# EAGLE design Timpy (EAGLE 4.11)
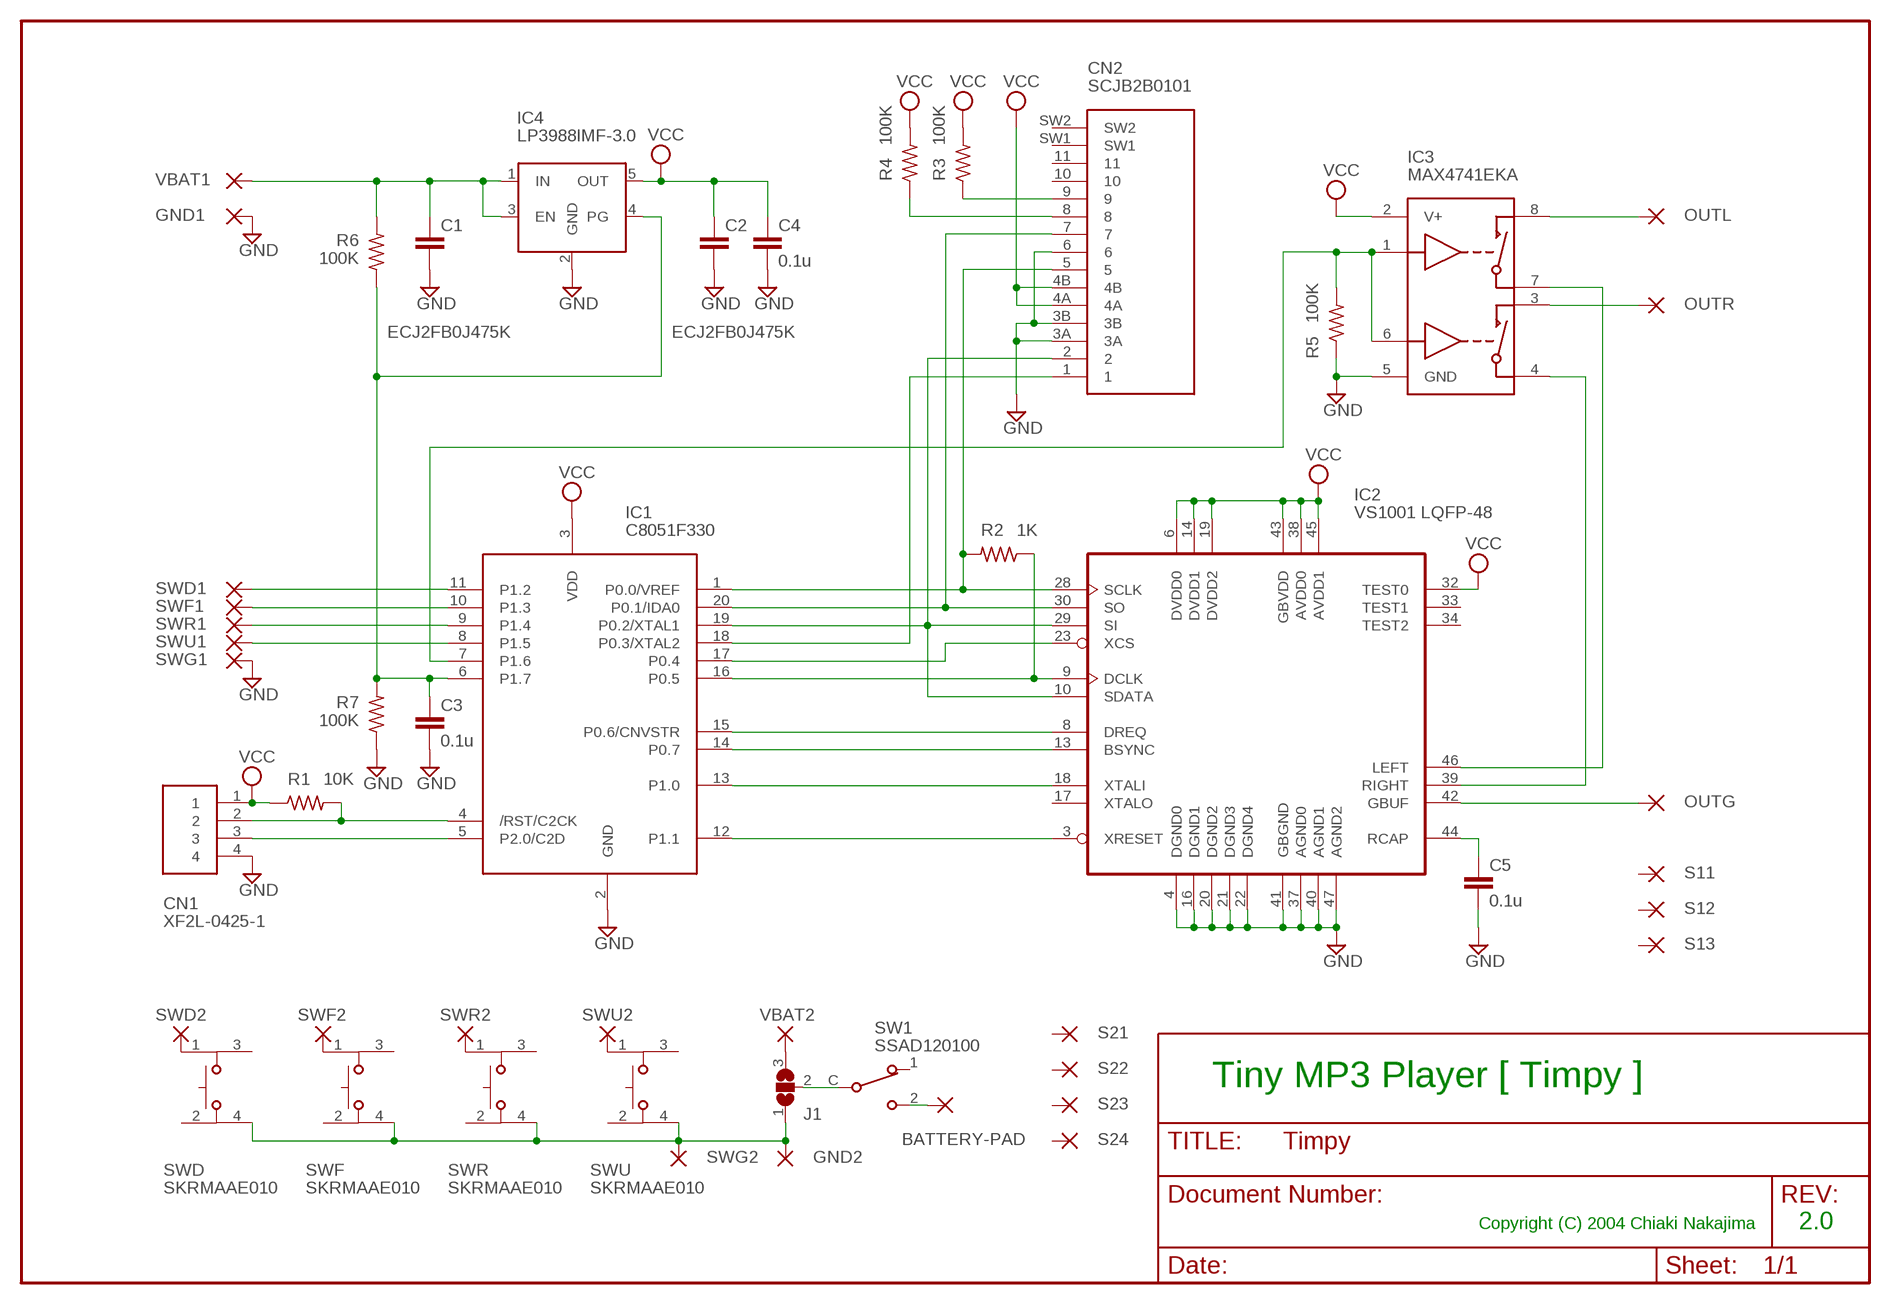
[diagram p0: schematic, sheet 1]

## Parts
BATTERY-PAD  SMD2  [SMD2]
C1  ECJ2FB0J475K  C-EUC2012  [C2012]
C2  ECJ2FB0J475K  C-EUC2012  [C2012]
C3  0.1u  C-EUC1005  [C1005]
C4  0.1u  C-EUC1005  [C1005]
C5  0.1u  C-EUC1005  [C1005]
CN1  XF2L-0425-1  [XF2L-0425-1]
CN2  SCJB2B0101  SCJB2B010X  [SCJB2B010X]
GND1  0.6/0.45  [0.6/0.45]
GND2  0.6/0.45  [0.6/0.45]
IC1  C8051F330  C8051F33X  [MLP20]
IC2  VS1001 LQFP-48  VS1001-LQFP48  [LQFP-48]
IC3  MAX4741EKA  [SOT23-8L]
IC4  LP3988IMF-3.0  LP3988  [SOT23-5]
J1  SMD-J3  [SMD-J3-1005X2]
OUTG  0.6/0.45  [0.6/0.45]
OUTL  0.6/0.45  [0.6/0.45]
OUTR  0.6/0.45  [0.6/0.45]
R1  10K  R-US_R1005  [R1005]
R2  1K  R-US_R1005  [R1005]
R3  100K  R-US_R1005  [R1005]
R4  100K  R-US_R1005  [R1005]
R5  100K  R-US_R1005  [R1005]
R6  100K  R-US_R1005  [R1005]
R7  100K  R-US_R1005  [R1005]
S11  0.6/0.45  [0.6/0.45]
S12  0.6/0.45  [0.6/0.45]
S13  0.6/0.45  [0.6/0.45]
S21  0.6/0.45  [0.6/0.45]
S22  0.6/0.45  [0.6/0.45]
S23  0.6/0.45  [0.6/0.45]
S24  0.6/0.45  [0.6/0.45]
SW1  SSAD120100  [SSAD120100]
SWD  SKRMAAE010  [SKRMAAE010]
SWD1  0.6/0.45  [0.6/0.45]
SWD2  0.6/0.45  [0.6/0.45]
SWF  SKRMAAE010  [SKRMAAE010]
SWF1  0.6/0.45  [0.6/0.45]
SWF2  0.6/0.45  [0.6/0.45]
SWG1  0.6/0.45  [0.6/0.45]
SWG2  0.6/0.45  [0.6/0.45]
SWR  SKRMAAE010  [SKRMAAE010]
SWR1  0.6/0.45  [0.6/0.45]
SWR2  0.6/0.45  [0.6/0.45]
SWU  SKRMAAE010  [SKRMAAE010]
SWU1  0.6/0.45  [0.6/0.45]
SWU2  0.6/0.45  [0.6/0.45]
VBAT1  0.6/0.45  [0.6/0.45]
VBAT2  0.6/0.45  [0.6/0.45]

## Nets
BATTERY-PAD: BATTERY-PAD.1(P) SW1.2
GND: C1.2 C2.2 C3.2 C4.2 C5.2 CN1.4 CN2.3A CN2.3B CN2.6 GND1.P$1(P) IC1.2(GND) IC2.4(DGND0) IC2.16(DGND1) IC2.20(DGND2) IC2.21(DGND3) IC2.22(DGND4) IC2.37(AGND0) IC2.40(AGND1) IC2.41(GBGND) IC2.47(AGND2) IC3.5(GND) IC4.2(GND) R5.1 R7.1 SWG1.P$1(P)
GND2 [Power]: GND2.P$1(P) J1.1 SWD.4 SWF.4 SWG2.P$1(P) SWR.4 SWU.4
N$1: CN1.3 IC1.5(P2.0/C2D)
N$2: SWD2.P$1(P) SWD.1
N$3: CN1.2 IC1.4(/RST/C2CK) R1.2
N$4: CN2.9 R3.1
N$5: CN2.8 R4.1
N$6: CN2.5 IC1.1(P0.0/VREF) IC2.28(SCLK) R2.2
N$7: IC1.16(P0.5) IC2.9(DCLK) R2.1
N$8: CN2.7 IC1.20(P0.1/IDA0) IC2.30(SO)
N$9: CN2.2 IC1.19(P0.2/XTAL1) IC2.10(SDATA) IC2.29(SI)
N$10: CN2.1 IC1.18(P0.3/XTAL2)
N$11: IC1.17(P0.4) IC2.23(XCS)
N$12: IC1.15(P0.6/CNVSTR) IC2.8(DREQ)
N$13: IC1.14(P0.7) IC2.13(BSYNC)
N$14: IC1.13(P1.0) IC2.18(XTALI)
N$15: IC1.12(P1.1) IC2.3(XRESET)
N$16: IC1.7(P1.6) IC3.1(IN1) IC3.6(IN2) R5.2
N$17 [Analog Out]: IC2.46(LEFT) IC3.7(COM1)
N$18 [Analog Out]: IC2.39(RIGHT) IC3.4(COM2)
N$19: C3.1 IC1.6(P1.7) IC4.4(PG) R6.1 R7.2
N$20: C5.1 IC2.44(RCAP)
N$22: C1.1 IC4.1(IN) IC4.3(EN) R6.2 VBAT1.P$1(P)
N$23 [Analog Out]: IC2.42(GBUF) OUTG.P$1(P)
N$24 [Analog Out]: IC3.8(NO1) OUTL.P$1(P)
N$25 [Analog Out]: IC3.3(NO2) OUTR.P$1(P)
N$26: IC1.11(P1.2) SWD1.P$1(P)
N$27: IC1.10(P1.3) SWF1.P$1(P)
N$28: IC1.9(P1.4) SWR1.P$1(P)
N$29: IC1.8(P1.5) SWU1.P$1(P)
N$30: SWF2.P$1(P) SWF.1
N$31: SWR2.P$1(P) SWR.1
N$32: SWU2.P$1(P) SWU.1
N$34 [Power]: J1.2 SW1.C
N$35 [Power]: J1.3 VBAT2.P$1(P)
VCC [Power]: C2.1 C4.1 CN1.1 CN2.4A CN2.4B IC1.3(VDD) IC2.6(DVDD0) IC2.14(DVDD1) IC2.19(DVDD2) IC2.32(TEST0) IC2.38(AVDD0) IC2.43(GBVDD) IC2.45(AVDD1) IC3.2(V+) IC4.5(OUT) R1.1 R3.2 R4.2
Unconnected: CN2.10 CN2.11 CN2.SW1 CN2.SW2 IC2.17(XTALO) IC2.33(TEST1) IC2.34(TEST2) S11.P$1(P) S12.P$1(P) S13.P$1(P) S21.P$1(P) S22.P$1(P) S23.P$1(P) S24.P$1(P) SW1.1 SWD.2 SWD.3 SWF.2 SWF.3 SWR.2 SWR.3 SWU.2 SWU.3

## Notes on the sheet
- Tiny MP3 Player [ Timpy ]
- Copyright (C) 2004 Chiaki Nakajima | 2.0

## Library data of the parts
BATTERY-PAD = wirepad:SMD2: SMD PAD
C1-C5 = rcl:C-EU: CAPACITOR, European symbol
CN1 = conn-omron-xf2l:XF2L-0425-1: 4P
CN2 = conn-alps-miniSD:SCJB2B010X: SCJB2B0101/2 miniSD connector
GND1 GND2 OUTG OUTL OUTR S11-S13 S21-S24 SWD1 SWD2 SWF1 SWF2 SWG1 SWG2 SWR1 SWR2 SWU1 SWU2 VBAT1 VBAT2 = pads:0.6/0.45: 0.6mm/0.45mm Through-Hole Pad
IC1 = cygnal_33x:C8051F33X: Cygnal C8051F330/1 microcontroller
IC2 = vs1001-lqfp:VS1001-LQFP48: VS1001 MP3 Decoder (LQFP-48)
IC3 = max4741:MAX4741E: Dual SPST Analog Switches on SOT23-8 Package
IC4 = lp3988:LP3988: National Semiconductor LP3988 Jul 07, 2004 Chiaki Nakajima http://www.chiaki.cc chi@chiaki.cc
J1 = pads:SMD-J3: SMD Jumper 3P
R1-R7 = rcl:R-US_: RESISTOR, American symbol
SW1 = switch-alps-tact:SSAD120100: Slide Switch SPDT SSAD120100
SWD SWF SWR SWU = switch-alps-tact:SKRMAAE010: Tact Switch SKRMAAE010

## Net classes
1 Analog Out: width 0.2 mm
2 Power: width 0.3 mm

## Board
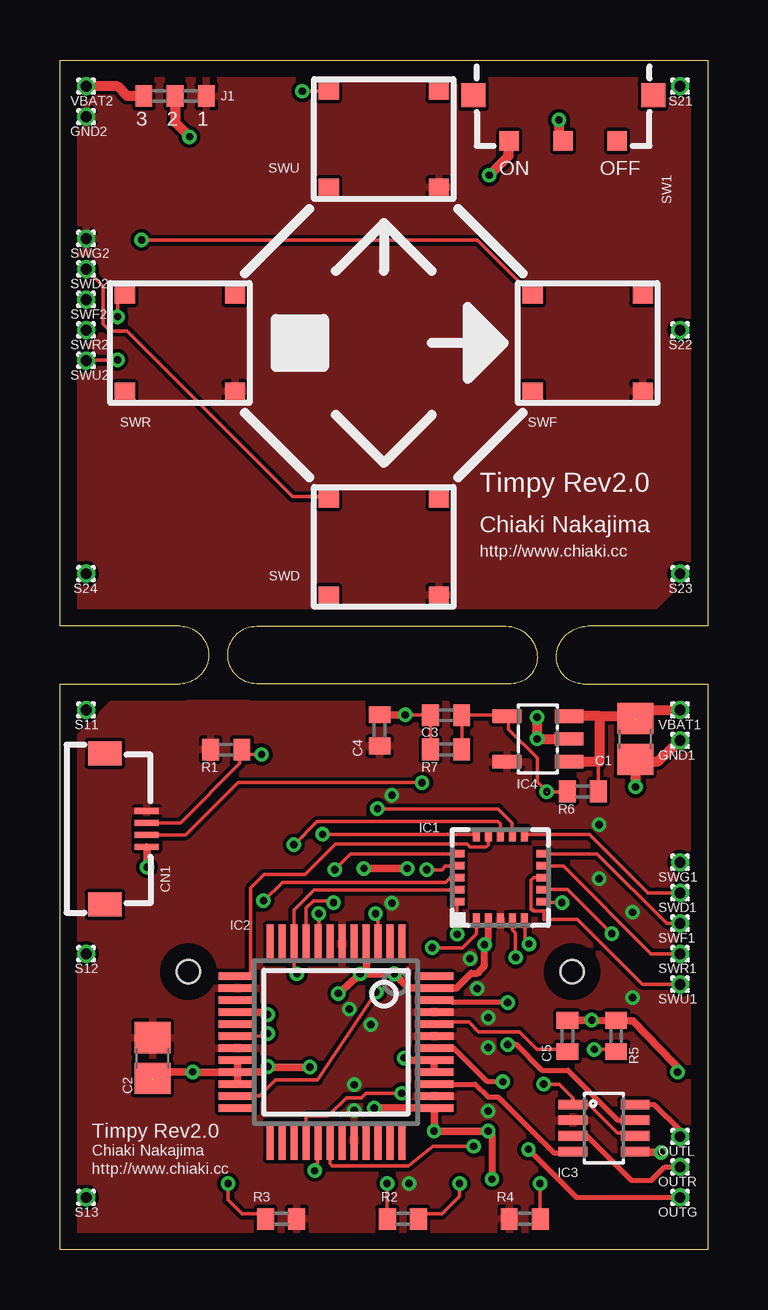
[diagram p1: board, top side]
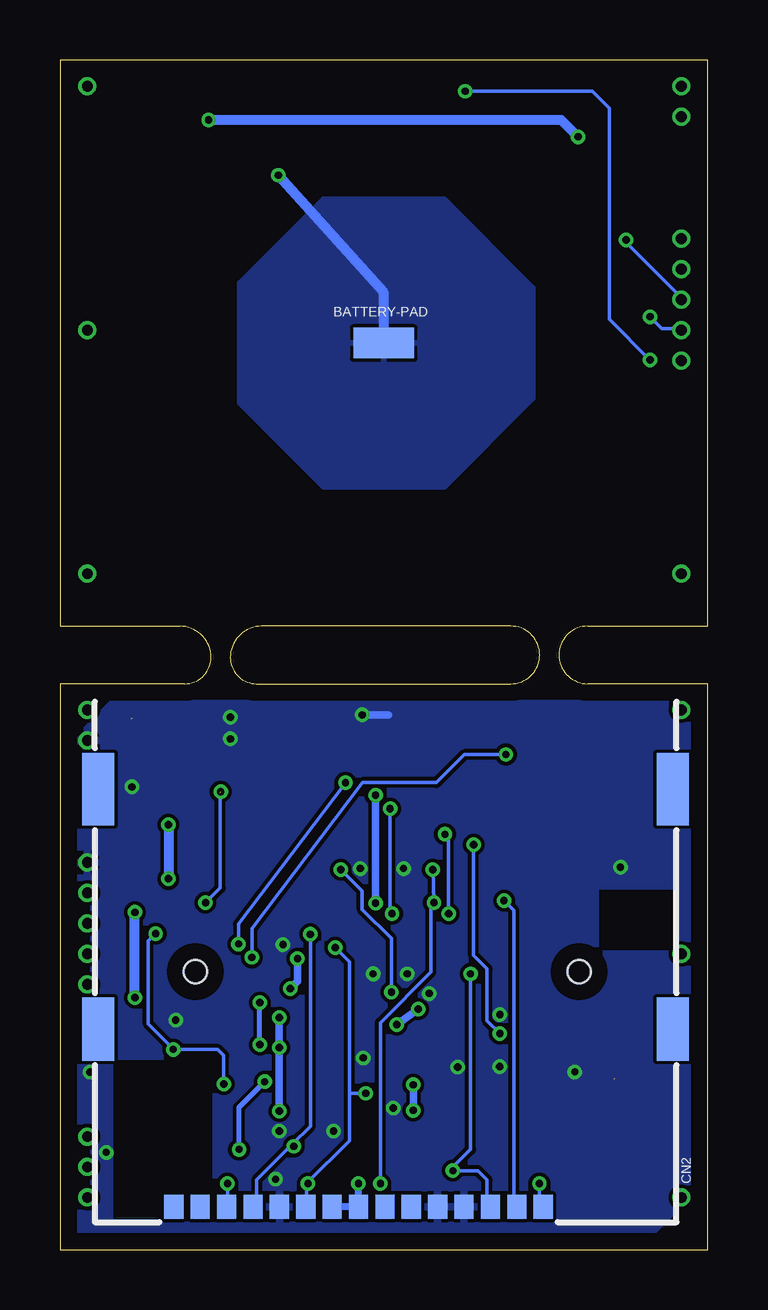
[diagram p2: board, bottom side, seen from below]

Size 27 x 49.6 mm. Coordinates in mm from the lower left corner, seen from the top.
Outline: 0,0 0,23.6 5,23.6 arc90 6.2,24.8 arc90 5,26 0,26 0,49.6 27,49.6 27,26 22,26 arc90 20.7,24.7 arc90 21.8,23.6 27,23.6 27,0 0,0
Outline: 7,24.8 arc-90 8.2,26 18.6,26 arc-90 19.9,24.7 arc-90 18.8,23.6 8.2,23.6 arc-90 7,24.8
Copper layers (1*16): Top 0.035mm / dielectric 1.5mm / Bottom 0.035mm
Design rules "p-ban": minimum track width 0.15mm, minimum drill 0.3mm, track to track 0.15mm, track to pad 0.15mm, pad to pad 0.15mm, via to via 0.15mm, smd to smd 0.15mm, copper to edge 0.7mm, drill to drill 0.45mm, minimum pad ring 0.15mm, minimum via ring 0.15mm, stop-mask expansion 4mil, vias tented up to drill 0mil, thermal gap 0.15mm

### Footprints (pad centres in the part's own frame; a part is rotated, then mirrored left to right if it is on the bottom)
SMD2 = smd 1.27 x 2.54: 1 0,0
C2012 = smd 1.3 x 1.5: 1 -0.85,0; 2 0.85,0
C1005 = smd 0.7 x 0.9: 1 -0.65,0; 2 0.65,0
XF2L-0425-1 = smd 0.25 x 1: 1 -0.75,0.5; 2 -0.25,0.5; 3 0.25,0.5; 4 0.75,0.5 | smd 1 x 1.4: F1 -3.15,-1.25; F2 3.15,-1.25
SCJB2B010X = smd 0.8 x 1: 1 -6.35,0; 2 -5.25,0; 3A -4.15,0; 3B -3.05,0; 4A 0.25,0; 4B 1.35,0; 5 2.45,0; 6 3.55,0; 7 4.65,0; 8 5.75,0; 9 -7.45,0; 10 -1.95,0; 11 -0.85,0; SW1 6.85,0; SW2 7.95,0 | smd 1.35 x 2.6: F1 -12.85,-7.4; F2 11.1,-7.4 | smd 1.35 x 3: F3 -12.85,-17.4; F4 11.1,-17.4 | hole 0.95: 7.05,-9.8; -8.95,-9.8
0.6/0.45 = drill 0.45 pad 0.6 round: P$1 0,0
MLP20 = smd 0.6 x 0.3: 1 -1.8,1; 2 -1.8,0.5; 3 -1.8,0; 4 -1.8,-0.5; 5 -1.8,-1; 11 1.8,-1; 12 1.8,-0.5; 13 1.8,0; 14 1.8,0.5; 15 1.8,1 | smd 0.3 x 0.6: 6 -1,-1.8; 7 -0.5,-1.8; 8 0,-1.8; 9 0.5,-1.8; 10 1,-1.8; 16 1,1.8; 17 0.5,1.8; 18 0,1.8; 19 -0.5,1.8; 20 -1,1.8
LQFP-48 = smd 0.3 x 1.6: 1 -2.75,-4.1; 2 -2.25,-4.1; 3 -1.75,-4.1; 4 -1.25,-4.1; 5 -0.75,-4.1; 6 -0.25,-4.1; 7 0.25,-4.1; 8 0.75,-4.1; 9 1.25,-4.1; 10 1.75,-4.1; 11 2.25,-4.1; 12 2.75,-4.1; 25 2.75,4.1; 26 2.25,4.1; 27 1.75,4.1; 28 1.25,4.1; 29 0.75,4.1; 30 0.25,4.1; 31 -0.25,4.1; 32 -0.75,4.1; 33 -1.25,4.1; 34 -1.75,4.1; 35 -2.25,4.1; 36 -2.75,4.1 | smd 1.6 x 0.3: 13 4.1,-2.75; 14 4.1,-2.25; 15 4.1,-1.75; 16 4.1,-1.25; 17 4.1,-0.75; 18 4.1,-0.25; 19 4.1,0.25; 20 4.1,0.75; 21 4.1,1.25; 22 4.1,1.75; 23 4.1,2.25; 24 4.1,2.75; 37 -4.1,2.75; 38 -4.1,2.25; 39 -4.1,1.75; 40 -4.1,1.25; 41 -4.1,0.75; 42 -4.1,0.25; 43 -4.1,-0.25; 44 -4.1,-0.75; 45 -4.1,-1.25; 46 -4.1,-1.75; 47 -4.1,-2.25; 48 -4.1,-2.75
SOT23-8L = smd 0.4 x 1.2: 1 -0.95,-1.3; 2 -0.3,-1.3; 3 0.35,-1.3; 4 1,-1.3; 5 1,1.3; 6 0.35,1.3; 7 -0.3,1.3; 8 -0.95,1.3
SOT23-5 = smd 0.55 x 1.2: 1 -0.95,-1.3; 2 0,-1.3; 3 0.95,-1.3; 4 0.95,1.3; 5 -0.95,1.3
SMD-J3-1005X2 = smd 0.7 x 0.9: 1 -1.3,0; 2 0,0; 3 1.3,0
R1005 = smd 0.7 x 0.9: 1 -0.65,0; 2 0.65,0
SSAD120100 = smd 0.8 x 0.8: 1 -2.25,1.9; 2 2.25,1.9; C 0,1.9 | smd 1 x 1: F1 -3.75,0; F2 3.75,0
SKRMAAE010 = smd 0.85 x 0.7: 1 -2.3,2; 2 -2.3,-2; 3 2.3,2; 4 2.3,-2

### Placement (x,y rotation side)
BATTERY-PAD  13.5,37.8 270 bottom
C1  23.98,21.3 270 top
C2  3.86,8 270 top
C3  16.1,22.29 180 top
C4  13.33,21.66 90 top
C5  21.16,8.92 90 top
CN1  3.12,17.55 270 top
CN2  14.3,1.8 180 bottom
GND1  25.86,21.23 180 top
GND2  1.09,47.23 180 top
IC1  18.36,15.52 90 top
IC2  11.51,8.66 180 top
IC3  22.68,5.11 270 top
IC4  19.93,21.3 90 top
J1  4.8,48.1 180 top
OUTG  25.86,2.18 180 top
OUTL  25.86,4.72 180 top
OUTR  25.86,3.45 180 top
R1  6.93,20.85 0 top
R2  14.3,1.3 0 top
R3  9.22,1.3 0 top
R4  19.38,1.3 180 top
R5  23.19,8.92 270 top
R6  21.8,19.11 0 top
R7  16.1,20.86 0 top
S11  1.09,22.5 180 top
S12  1.09,12.34 180 top
S13  1.09,2.18 180 top
S21  25.86,48.5 180 top
S22  25.86,38.34 180 top
S23  25.86,28.18 180 top
S24  1.09,28.18 180 top
SW1  20.98,48.12 180 top
SWD  13.5,29.3 0 top
SWD1  25.86,14.88 180 top
SWD2  1.09,40.88 180 top
SWF  22,37.8 0 top
SWF1  25.86,13.61 180 top
SWF2  1.09,39.61 180 top
SWG1  25.86,16.15 180 top
SWG2  1.09,42.15 180 top
SWR  5,37.8 0 top
SWR1  25.86,12.34 180 top
SWR2  1.09,38.34 180 top
SWU  13.5,46.3 0 top
SWU1  25.86,11.07 180 top
SWU2  1.09,37.07 180 top
VBAT1  25.86,22.5 180 top
VBAT2  1.09,48.5 180 top

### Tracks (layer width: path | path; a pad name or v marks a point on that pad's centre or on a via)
BATTERY-PAD  (via drill 0.3)
  Top 0.406: SW1.2 18.7,45.6 v17.9,44.8
  Bottom 0.406: v17.9,44.8 13.5,39.9 BATTERY-PAD.1
  pour Bottom: 11,43.8 7.3,40.1 7.3,35.5 11,31.8 16,31.8 19.5,35.3 19.5,40.3 16,43.8
GND  (via drill 0.3)  (1 unrouted)
  Top 0.15: v14.4,22.3 15.4,22.3 | 15.4,22.3 15.5,22.3 15.49,22.29 C3.2 15.41,22.29 15.4,22.3 | R7.1 15.45,22.25 15.4,22.3
  Top 0.3: IC1.2 17.86,12.98 v17.7,12.72 17.7,11.86 17.4,11.53 17.14,11.53 16.54,10.92 16.38,10.92 | v18.01,2.95 18.01,4.8 v17.86,4.95
  Top 0.305: IC2.40 15.6,7.54 15.6,7.77 IC2.41 14.45,7.9 v14.35,8 | 23.88,9.55 23.77,9.55 23.15,9.56 R5.1 | 23.88,9.55 25.6,7.77 25.76,7.62 v25.76,7.42 | 23.88,9.55 v22.17,9.58 21.59,9.58 C5.2 | v3.63,15.95 3.63,16.51 CN1.4 | v25.07,4.06 24.31,4.06 IC3.5 | 12.78,11.51 IC2.4 | v8.66,9.8 8.56,9.91 IC2.16 | 12.78,11.51 v13.95,11.51 14.53,10.92 16.08,10.92 | IC2.37 15.61,4.96 v15.6,4.95 v17.86,4.95 | 12.78,11.51 v12.52,11.51 v11.61,10.69 | IC2.21 8.46,7.42 8.66,7.62 | 8.66,7.62 v8.66,7.64 | 3.89,7.11 4.19,7.42 v5.54,7.42 v5.54,7.41 IC2.21 | IC2.20 7.39,7.9 7.41,7.88 | IC2.21 7.41,7.88 | IC2.21 IC2.22 | IC2.21 7.41,7.43 7.39,7.44 7.41,7.46 7.41,7.88 | 8.66,7.62 v10.41,7.62 | v13.11,5.92 15.62,5.92 | 16.08,10.92 16.38,10.92 | IC2.47 16.07,10.91 16.08,10.92 | v12.68,15.9 v14.48,15.9 | C4.2 v14.4,22.3
  Top 0.406: 23.93,20.26 24.03,20.26 24.4,20.28 24.4,20.36 24.96,20.36 GND1.P$1 | C1.2 24,19.95 v24,19.3 | v19.9,22.2 v19.9,21.3 IC4.2
  Bottom 0.305: 14.21,22.3 14.42,22.32 | 14.21,22.3 13.3,22.3 | v14.4,22.3 14.21,22.3
  pour Bottom: 26.77,20.83 26.77,0.25 2.79,0.25 0.25,2.79 0.25,22.77 24.83,22.77
GND2
  pour Top: 0.25,26.85 0.25,46.83 2.79,49.37 26.77,49.37 26.77,28.79 24.83,26.85
N$1  (via drill 0.3)
  Top 0.15: v15.1,19.47 15.09,19.48 7.42,19.48 5.23,17.3 CN1.3 | v19.56,12.75 19.38,12.93 19.38,13.72 IC1.5
  Bottom 0.15: v19.56,12.75 19.56,13.59 v15.1,19.47
N$2
  Top 0.15: SWD2.P$1 1.8,40.18 1.8,38.6 2.1,38.3 2.8,38.3 9.7,31.4 11.1,31.4 SWD.1
N$3  (via drill 0.3)  (1 unrouted)
  Top 0.15: v8.41,20.65 7.92,20.65 R1.2 7.49,20.42 7.49,20.27 5.03,17.8 CN1.2 | v19,12.19 19,13.18
  Top 0.152: IC1.4 18.86,13.34 19,13.21 19,13.18
  Bottom 0.15: v8.41,20.65 10.13,20.65 11.3,19.48 14.38,19.48 19,13.4 | v19,12.19 19,13.41
N$4  (via drill 0.3)
  Top 0.15: v7.01,2.77 7.01,2.08 7.59,1.5 8.23,1.5 R3.1
  Bottom 0.15: v7.01,2.77 7.01,2.29 CN2.9
N$5  (via drill 0.3)
  Top 0.15: v20.02,2.77 20.02,1.73 R4.1
  Bottom 0.15: v20.02,2.77 20.02,2.29 CN2.8
N$6  (via drill 0.3)
  Top 0.15: v15.52,12.6 16.79,12.6 17.36,13.17 IC1.1 | v16.66,2.77 16.66,2.23 15.93,1.5 15.29,1.5 R2.2 | v14.25,6.53 12.75,6.53 12.57,6.35 11.94,6.35 11.18,5.59 10.26,5.59 10.26,5.49 IC2.28
  Bottom 0.15: v15.52,12.6 14.94,12.01 14.94,6.53 | 16.71,2.77 16.71,2.29 CN2.5 | 14.94,6.53 14.94,4.55 16.71,2.77 | v16.66,2.77 16.71,2.77 | 14.94,6.53 v14.25,6.53
N$7  (via drill 0.3)
  Top 0.15: v11.46,15.85 12.12,16.51 16.38,16.51 IC1.16 | v11.4,14.48 11.33,14.55 10.57,14.55 10.26,14.25 10.26,13.54 IC2.9 | v13.64,2.77 13.64,1.73 R2.1
  Bottom 0.15: v11.46,15.85 11.4,14.53 v11.4,14.48 11.53,14.2 11.53,11.58 13.64,9.47 v13.64,2.77
N$8  (via drill 0.3)
  Top 0.15: v16.56,13.16 16.56,14.38 IC1.20 | v17.25,4.32 15.54,4.32 14.53,3.5 11.35,3.5 11.25,3.61 IC2.30
  Bottom 0.15: 16.56,13.08 v16.56,13.16 16.56,5.16 17.32,4.39 | 17.32,4.39 18.8,2.92 18.8,2.29 CN2.7 | v17.25,4.32 17.32,4.39
N$9  (via drill 0.3)
  Top 0.15: v10.62,3.3 10.62,3.5 10.74,3.63 10.74,3.79 IC2.29 | IC1.19 16.28,15.01 10.59,15.01 9.75,14.17 IC2.10 9.75,11.79 v9.88,11.51
  Bottom 0.15: CN2.2 9.2,2.29 9.2,2.92 9.58,3.3 v10.62,3.3 10.49,3.58 9.88,4.19 v9.88,11.51
N$10  (via drill 0.3)
  Top 0.15: IC1.18 16.28,15.52 16.08,15.32 9.27,15.32 v8.48,14.55
  Bottom 0.15: v8.48,14.55 8.08,14.15 8.08,2.29 CN2.1
N$11  (via drill 0.3)
  Top 0.15: v15.29,15.85 15.93,15.85 16.08,16 16.54,16 IC1.17 | v13.18,10.74 10.74,7.09 8.99,7.09 8.33,6.43 8.05,6.43 IC2.23
  Bottom 0.15: v15.29,15.85 14.4,14.96 14.4,14.2 13.18,12.98 v13.18,10.74
N$12  (via drill 0.3)
  Top 0.15: v10.95,17.32 17.22,17.32 IC1.15 | v10.79,14.02 10.79,13.54 IC2.8
  Bottom 0.15: v10.95,17.32 10.79,17.17 v10.79,14.02
N$13
  Top 0.15: IC1.14 17.86,16.89 17.75,16.79 17.09,16.79 16.97,16.92 11.48,16.92 10.21,15.65 8.51,15.65 7.95,15.09 7.95,11.4 IC2.13
N$14  (via drill 0.3)
  Top 0.15: v9.75,16.89 10.72,17.86 18.26,17.86 18.36,17.75 IC1.13 | v8.66,9.02 8.38,8.91 IC2.18
  Bottom 0.15: v9.75,16.89 9.75,12.27 9.2,11.71 9.2,9.55 v8.66,9.02
N$15  (via drill 0.3)
  Top 0.15: v13.23,18.39 18.26,18.39 18.85,17.8 18.85,17.32 IC1.12 | v13.16,14.02 13.26,13.74 IC2.3
  Bottom 0.15: v13.23,18.39 13.23,14.3 v13.16,14.02
N$16  (via drill 0.3)
  Top 0.15: IC3.6 23.88,4.88 23.24,4.88 22.07,6.04 IC3.1 21.39,6.35 20.83,6.91 v20.17,6.91 | v23.01,13.18 21.16,15.04 20.45,15.04 IC1.7 | v22.28,8.36 22.76,8.36 R5.2
  Bottom 0.15: v23.01,13.18 23.32,12.88 23.32,9.42 22.28,8.38 v22.28,8.36 20.42,8.36 20.17,8.1 v20.17,6.91
N$17  (via drill 0.3)
  Top 0.2: v18.67,8.56 19.02,8.56 20.09,7.49 21.18,7.49 23.27,5.41 IC3.7 | v18.67,10.31 16.38,10.31 IC2.46
  Bottom 0.2: v18.67,8.56 v18.67,10.31
N$18
  Top 0.2: IC3.4 20.8,4.04 20.6,4.04 18.26,6.38 17.86,6.38 17.32,6.91 16.31,6.91 IC2.39
N$19  (via drill 0.3)  (1 unrouted)
  Top 0.15: v20.93,14.48 20.45,14.48 IC1.6 | 16.8,22.3 C3.1 16.79,22.29 16.8,22.3 | 16.8,22.3 18.6,22.3 | 18.7,22.25 18.7,21.7 19.9,20.5 19.9,19.5 v20.3,19.1 21.1,19.1 21.11,19.11 R6.1 | R7.2 16.75,22.25 16.8,22.3
  Top 0.406: 18.6,22.3 18.6,22.25 IC4.4 18.7,22.25
  Bottom 0.15: v20.93,14.48 v20.92,14.48 20.32,15.08 20.32,19.05
N$20
  Top 0.15: C5.1 20.73,8.36 19.89,8.36 19.15,9.09 17.45,9.09 17.04,9.5 16.38,9.5 IC2.44
N$22  (1 unrouted)
  Top 0.15: 22.5,20.35 22.5,20.3 22.45,20.25 R6.2
  Top 0.406: 24.03,22.12 24.03,22.5 VBAT1.P$1 | C1.1 23.9,22.05 23.7,22.25 22.5,22.25 | 22.5,22.25 IC4.3 | IC4.1 22.5,20.35 22.5,22.25
N$23  (via drill 0.3)
  Top 0.2: v18.47,7.01 17.83,7.01 16.43,8.41 16.23,8.41 IC2.42 | v19.53,4.19 21.54,2.18 24.26,2.18
  Top 0.203: 24.26,2.18 OUTG.P$1
  Bottom 0.2: v18.47,7.01 19.53,5.94 v19.53,4.19
N$24
  Top 0.203: IC3.8 24.78,6.05 25.86,4.98 OUTL.P$1
N$25
  Top 0.2: 23.82,2.9 21.97,4.75 IC3.3
  Top 0.203: OUTR.P$1 25.22,3.45 24.66,2.9 23.82,2.9
N$26
  Top 0.15: 24.89,14.88 24.51,14.88 22.07,17.32 19.51,17.32 IC1.11
  Top 0.152: 24.89,14.88 SWD1.P$1
N$27
  Top 0.15: 25.3,13.61 22.38,16.51 20.37,16.51 IC1.10
  Top 0.152: 25.3,13.61 SWF1.P$1
N$28
  Top 0.15: 24.64,12.34 20.98,16 20.37,16 IC1.9
  Top 0.152: 24.64,12.34 SWR1.P$1
N$29
  Top 0.15: 24.28,11.07 21.57,13.77 20.17,13.77 20.17,14.12 19.74,14.12 19.74,14.17 19.68,14.17 19.68,14.22 19.63,14.22 19.63,15.39 19.76,15.52 IC1.8
  Top 0.152: 24.28,11.07 SWU1.P$1
N$30  (via drill 0.3)
  Top 0.15: SWF.1 17.4,42.1 v3.4,42.1
  Bottom 0.15: SWF2.P$1 1.09,39.69 3.4,42 v3.4,42.1
N$31  (via drill 0.3)
  Top 0.15: SWR.1 2.4,39.8 v2.4,38.9
  Bottom 0.15: SWR2.P$1 1.1,38.35 1.1,38.4 1.9,38.4 v2.4,38.9
N$32  (via drill 0.3)
  Top 0.15: v10.1,48.3 SWU.1 | SWU2.P$1 1.09,37.09 1.1,37.1 v2.4,37.1
  Bottom 0.15: v10.1,48.3 4.8,48.3 4.1,47.6 4.1,38.8 v2.4,37.1
N$34  (via drill 0.3)
  Top 0.406: SW1.C 20.98,46.2 20.8,46.3 v20.8,47.1 | J1.2 4.8,47 v5.4,46.4
  Bottom 0.406: v5.4,46.4 6.1,47.1 v20.8,47.1
N$35
  Top 0.406: J1.3 2.8,48.1 2.4,48.5 VBAT2.P$1
VCC  (via drill 0.3)
  Top 0.305: v13.85,18.95 v13.84,18.95
  Bottom 0.3: CN2.4B CN2.4A 14.55,2.29 v14.55,2.77
  Bottom 0.305: v12.27,6.88 v12.27,5.82 | v17.86,5.79 v17.86,8.43 v17.86,9.68 | v17.4,10.9 17.09,11.2 v17.09,12.14 | v13.84,14.45 v13.84,18.95 | v12.06,10.03 v12.95,9.4
  Bottom 0.406: v22.48,17.73 v22.48,15.47 | v23.88,10.52 v23.88,14.07
  pour Top: 26.77,22.77 26.77,2.79 24.23,0.25 0.25,0.25 0.25,20.83 2.19,22.77

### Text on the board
tPlace: ON | OFF | Timpy Rev2.0 | Chiaki Nakajima | http://www.chiaki.cc | Timpy Rev2.0 | Chiaki Nakajima | http://www.chiaki.cc
Measures: 23.6mm | 23.6mm | 27.0mm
